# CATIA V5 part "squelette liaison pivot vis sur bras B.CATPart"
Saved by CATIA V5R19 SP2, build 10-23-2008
Part number: squelette liaison pivot vis sur bras B
Publications: "Axe 4", "Axe vis", "Plan.1"
Bounding box of the stored display mesh (mm): x -100 to 100, y 0 to 50, z 0 to 0
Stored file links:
  G:\EU_thinkMotion\CFAO_2010\MMS_groupe3\MMS_groupe3\A reprendre\mmugnier\Systeme_Cric_Y\Systeme_Cric_Y\squelette liaison pivot vis sur bras B.CATPart
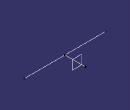
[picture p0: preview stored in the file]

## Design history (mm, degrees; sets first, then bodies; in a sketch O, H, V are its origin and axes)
Set1
  Line1 "Axe 4": type Normal, RefPoint {point type Coord, X 0, Y 0, Z 0}, RefSkin yz-plane, Start -100, End 100
  Line2 "Axe vis": type Normal, RefPoint {point type Coord, X 0, Y 0, Z 0}, RefSkin zx-plane, Start 0, End 50
  Plane1: type Offset, RefPlane zx-plane, Offset 30
Body1 (main body)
